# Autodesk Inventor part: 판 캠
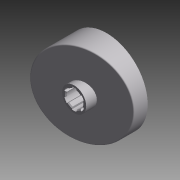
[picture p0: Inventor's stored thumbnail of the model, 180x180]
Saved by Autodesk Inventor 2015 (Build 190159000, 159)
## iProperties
Company: 한국ATC센터
Created: 2014-07
Part Number: 판 캠
Document SubType Name: 모델링
Designer: KYOUNG IL JANG
Material: Steel
Appearance: Aluminum - Flat
Mass: 681.587 g
Surface Area: 331.303 cm^2
Volume: 86.8264 cm^3
Density: 7.85 g/cm^3
Author: KYOUNG IL JANG
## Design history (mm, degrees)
node "작업 평면4"
sketch "스케치1"
  geometry: C1 r 44.5 at (0, 0); 1 further point
  constraints: 1 centre point, 1 coincident
  dimensions: "d25" = 89 diameter of C1
extrude "돌출1" new body sketch "스케치1" distance "d1" = 40; taper "d2" = 0 deg
sketch "스케치2"
  geometry: L1 (-44.5, 15)-(44.5, 38.847); L2 (-44.5, 0)-(-44.5, 40) reference; L3 (-44.5, 40)-(44.5, 40) reference; L4 (44.5, 0)-(44.5, 40) reference; 1 further point
  constraints: 2 end point, 2 point on line
  dimensions: "d26" = 15 distance of L2.start L1.start; "d27" = 75 deg angle of L1 L2
extrude "돌출2" cut sketch "스케치2" stored distance "d5" = 40; taper "d6" = 0 deg
node "작업 평면1"
sketch "스케치3"
  geometry: C1 r 13 at (0, 0); 1 further point
  constraints: 1 centre point, 1 coincident
  dimensions: "d9" = 26 diameter of C1
extrude "돌출3" join sketch "스케치3" distance "d10" = 38; taper "d11" = 0 deg
hole "구멍1" diameter "d14" = 18; stored, may be unused: countersink angle "d18" = 90 deg, drill point angle "d20" = 118 deg; dims "d12" = 10, "d13" = 10, "d15" = 6, "d16" = 4, "d17" = 2, "d19" = 8
feature "쉘2" dims "d29" = 5
sketch "스케치6"
  geometry: C1 r 17.5 at (0, 0); C2 r 14 at (0, 0) reference; 1 further point
  constraints: 1 centre point, 1 coincident
  dimensions: "d28" = 35 diameter of C1
extrude "돌출4" join sketch "스케치6" stored distance "d30" = 38; taper "d31" = 0 deg
fillet "모깎기1" dims "d32" = 3
chamfer "모따기1" distance "d21" = 1; stored, may be unused: second distance "d22" = 2, angle "d23" = 45 deg
feature "리브1" dims "d34" = 5, "d35" = 1, "d36" = 0
fillet "모깎기2" dims "d37" = 3
sketch "스케치8"
  geometry: L1 (2.5, 10.712)-(2.5, 8.646); L2 (-2.5, 10.712)-(-2.5, 8.646); A1 r 11 centre (0, 0) between (2.5, 10.712) and (-2.5, 10.712); A2 r 9 centre (0, 0) between (2.5, 8.646) and (-2.5, 8.646) reference; 1 further point
  constraints: 4 end point, 4 point on circle, 2 parallel, 1 centre point, 1 coincident, 1 vertical
  dimensions: "d41" = 22 diameter of A1; "d42" = 5 distance between parallel lines of L1 L2
extrude "돌출5" cut sketch "스케치8" stored distance "d43" = 38; taper "d44" = 0 deg
fillet "모깎기3" dims "d48" = 1
node "솔리드1"
node "솔리드 본체"
node "곡면 본체"
pattern_circular "원형 패턴1" dims angle "d39" = 360 deg
pattern_circular "원형 패턴2" dims angle "d46" = 360 deg
node "솔리드2"
sketch "스케치7"
  geometry: L1 (-12.374, 12.374)-(-27.931, 27.931); A1 r 39.5 centre (0, 0) between (-27.931, 27.931) and (0, 39.5) reference; 2 further points
  constraints: 2 end point, 2 point on circle, 1 point on line, 1 vertical alignment, 2 other
  dimensions: "d33" = 45 deg dimension on point (0, 0) L1.start A1.end
